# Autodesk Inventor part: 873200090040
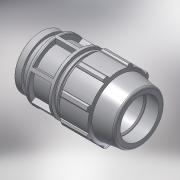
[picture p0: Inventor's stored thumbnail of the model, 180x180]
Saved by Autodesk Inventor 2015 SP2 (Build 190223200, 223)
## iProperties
Created: 2017-02
Part Number: 873200090040
Material: PVC-Piping
Description: PLASSON SHOULDERED ADAPTOR 90-4"
Document SubType Name: Modeling
Designer: KIM
Mass: 92.6774 g
Surface Area: 199.44 cm^2
Volume: 66.1981 cm^3
Density: 1.4 g/cm^3
Appearance: Smooth - White
Author: KIM
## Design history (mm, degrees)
derived "87320.ipt"
feature "Solid1::87320.ipt"
tag "TaggingFeature1"
body "Solid1"
other parameters: "d4" = 32.85714, "d5" = 46, "d7" = 152, "d8" = 114, "d9" = 32.85714, "d11" = 8.21429, "d12" = 121.6, "d13" = 120 deg, "d14" = 117, "d15" = 8 deg, "d16" = 136.8, "d18" = 4.5, "d19" = 35 deg, "d20" = 17.5 deg, "d21" = 141.36, "d23" = 0, "d25" = 360 deg, "d27" = 3.04, "d34" = 7.6, "d36" = 0, "d42" = 69, "d43" = 4.56, "d46" = 2.7, "d49" = 169, "d53" = 1.8, "d55" = 360 deg, "d57" = 123, "d59" = 46, "d61" = 110.7, "d62" = 16, "d64" = 5.14286, "d66" = 129.96, "d67" = 5.14286, "d70" = 86.1, "d71" = 73.8, "d73" = 6.15, "d74" = 16, "E_" = 152, "l_" = 169, "L_" = 16, "B_" = 123, "d63" = 20.57143, "d72" = 18.45
